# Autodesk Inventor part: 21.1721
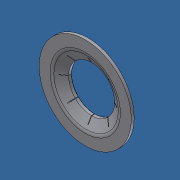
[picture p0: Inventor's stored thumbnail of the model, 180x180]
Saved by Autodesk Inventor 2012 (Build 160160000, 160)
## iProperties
Created: 2007-07
Part Number: 21.1721
Document SubType Name: Modeling
Designer: Andy Moles
Material: Steel
Mass: 0.62745 g
Surface Area: 3.6656 cm^2
Volume: 0.07993 cm^3
Density: 7.85 g/cm^3
Description: BEARING ASSEMBLY S WASHER
Author: Andy Moles
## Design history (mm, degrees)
sketch "Sketch1"
  geometry: L1 (4, 1.611)-(4, 1.114); L2 (8, 0.5)-(8, 0); L3 (4.076, 1.654)-(5.73, 0.646); L4 (6.25, 0.5)-(8, 0.5); L5 (4, 1.114)-(5.589, 0.146); L6 (6.11, 0)-(8, 0); L7 (0, 0)-(0, 5.16); A1 r 0.05 centre (4.05, 1.611) between (4.076, 1.654) and (4, 1.611); A2 r 1 centre (6.25, 1.5) between (5.73, 0.646) and (6.25, 0.5); A3 r 1 centre (6.11, 1) between (5.589, 0.146) and (6.11, 0); 1 further point
  constraints: 14 end point, 6 point on circle, 6 tangent, 3 centre point, 3 parallel, 2 perpendicular, 2 point on line, 1 horizontal alignment, 1 vertical
  dimensions: "d0" = 4 distance from line of L1 L7.start; "d1" = 8 distance of L2.end L7.start; "d2" = 0.5 distance of L2.start L2.end; "d4" = 1.7 vertical distance of L7.start point (4, 1.7); "d5" = 0.05 radius of A1; "d6" = 1 radius of A2; "d7" = 1 radius of A3; "d8" = 0.5 distance between parallel lines of L3 L5; "d9" = 1.75 distance of L4.start L2.start
revolve "Revolution1" sketch "Sketch1" stored, may be unused: angle "d10" = 90 deg
sketch "Sketch2"
  geometry: L1 (-0.05, 4.995)-(-0.05, 3.926); L2 (0.049, 4.991)-(0.049, 3.926); L3 (-0.05, 3.926)-(0.049, 3.926); C1 r 6.11 at (0, 0) reference; C2 r 4 at (0, 0) reference; A1 r 0.05 centre (0, 5) between (0.049, 4.991) and (-0.05, 4.995)
  constraints: 6 end point, 2 point on circle, 1 centre point, 1 parallel, 1 perpendicular, 1 vertical, 1 vertical alignment
  dimensions: "d11" = 5 distance of A1.centre C1.centre; "d12" = 0.05 radius of A1
extrude "Extrusion1" cut sketch "Sketch2" stored distance "d13" = 10; taper "d14" = 0 deg
pattern_circular "Circular Pattern1" dims angle "d16" = 360 deg
body "Solid1"
